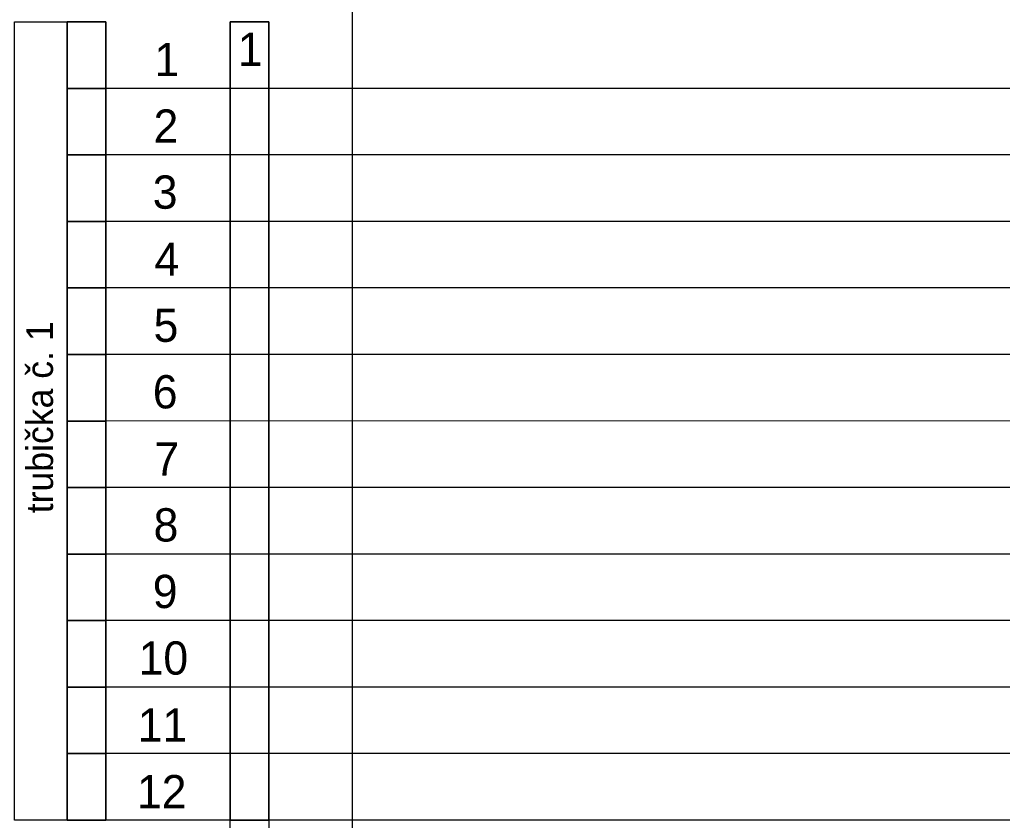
# Model space of a CAD drawing. Extents: x 1901 to 2519, y -3585 to -3154.
# Drawn here: x 2387.9 to 2439.8, y -3245.2 to -3202.9 of the extents above; entities that cross this region are included whole.
import ezdxf

# ---------------------------------------------------------------- set-up
doc = ezdxf.new("R2010")
doc.units = 0
doc.layers.add('rozvláknění', color=7, linetype='Continuous')

msp = doc.modelspace()

# ---------------------------------------------------------------- linework, layer by layer
at = {"layer": 'rozvláknění'}
for p, q in [((2487.131, -3206.524), (2392.43, -3206.525)), ((2487.131, -3210.042), (2392.43, -3210.043)), ((2487.131, -3213.56), (2392.43, -3213.561)), ((2487.131, -3217.078), (2392.43, -3217.079)), ((2487.131, -3220.596), (2392.43, -3220.598)), ((2487.131, -3224.115), (2392.43, -3224.116)), ((2487.131, -3227.633), (2392.43, -3227.634)), ((2487.131, -3231.151), (2392.43, -3231.152)), ((2487.131, -3234.669), (2392.43, -3234.67)), ((2487.131, -3238.187), (2392.43, -3238.189)), ((2487.131, -3241.706), (2392.43, -3241.707)), ((2487.131, -3245.224), (2392.43, -3245.225))]:
    msp.add_line(p, q, dxfattribs=at)
for points in [[(2371.457, -3178.543), (2405.455, -3178.542), (2405.455, -3379.276), (2371.457, -3379.276)], [(2387.602, -3203.007), (2390.389, -3203.007), (2390.389, -3245.221), (2387.602, -3245.221)], [(2390.389, -3203.007), (2392.43, -3203.007), (2392.43, -3206.525), (2390.389, -3206.525)], [(2390.389, -3203.007), (2392.43, -3203.007), (2392.43, -3206.525), (2390.389, -3206.525)], [(2401.054, -3287.479), (2399.013, -3287.479), (2399.013, -3203.007), (2401.054, -3203.007)], [(2401.054, -3245.225), (2399.013, -3245.225), (2399.013, -3203.007), (2401.054, -3203.007)], [(2390.389, -3206.525), (2392.43, -3206.525), (2392.43, -3210.043), (2390.389, -3210.043)], [(2390.389, -3206.525), (2392.43, -3206.525), (2392.43, -3210.043), (2390.389, -3210.043)], [(2390.389, -3210.043), (2392.43, -3210.043), (2392.43, -3213.561), (2390.389, -3213.561)], [(2390.389, -3210.043), (2392.43, -3210.043), (2392.43, -3213.561), (2390.389, -3213.561)], [(2390.389, -3213.561), (2392.43, -3213.561), (2392.43, -3217.079), (2390.389, -3217.079)], [(2390.389, -3213.561), (2392.43, -3213.561), (2392.43, -3217.079), (2390.389, -3217.079)], [(2390.389, -3217.079), (2392.43, -3217.079), (2392.43, -3220.598), (2390.389, -3220.598)], [(2390.389, -3217.079), (2392.43, -3217.079), (2392.43, -3220.598), (2390.389, -3220.598)], [(2390.389, -3220.598), (2392.43, -3220.598), (2392.43, -3224.116), (2390.389, -3224.116)], [(2390.389, -3220.598), (2392.43, -3220.598), (2392.43, -3224.116), (2390.389, -3224.116)], [(2390.389, -3224.116), (2392.43, -3224.116), (2392.43, -3227.634), (2390.389, -3227.634)], [(2390.389, -3224.116), (2392.43, -3224.116), (2392.43, -3227.634), (2390.389, -3227.634)], [(2390.389, -3227.634), (2392.43, -3227.634), (2392.43, -3231.152), (2390.389, -3231.152)], [(2390.389, -3227.634), (2392.43, -3227.634), (2392.43, -3231.152), (2390.389, -3231.152)], [(2390.389, -3231.152), (2392.43, -3231.152), (2392.43, -3234.67), (2390.389, -3234.67)], [(2390.389, -3231.152), (2392.43, -3231.152), (2392.43, -3234.67), (2390.389, -3234.67)], [(2390.389, -3234.67), (2392.43, -3234.67), (2392.43, -3238.189), (2390.389, -3238.189)], [(2390.389, -3234.67), (2392.43, -3234.67), (2392.43, -3238.189), (2390.389, -3238.189)], [(2390.389, -3238.189), (2392.43, -3238.189), (2392.43, -3241.707), (2390.389, -3241.707)], [(2390.389, -3238.189), (2392.43, -3238.189), (2392.43, -3241.707), (2390.389, -3241.707)], [(2390.389, -3241.707), (2392.43, -3241.707), (2392.43, -3245.225), (2390.389, -3245.225)], [(2390.389, -3241.707), (2392.43, -3241.707), (2392.43, -3245.225), (2390.389, -3245.225)]]:
    msp.add_lwpolyline(points, close=True, dxfattribs=at)
for points in [[(2390.389, -3206.525), (2392.43, -3206.525), (2392.43, -3203.007), (2390.389, -3203.007), (2390.389, -3206.525)], [(2390.389, -3206.525), (2392.43, -3206.525), (2392.43, -3203.007), (2390.389, -3203.007), (2390.389, -3206.525)], [(2390.389, -3206.525), (2392.43, -3206.525), (2392.43, -3203.007), (2390.389, -3203.007), (2390.389, -3206.525)], [(2390.389, -3206.525), (2392.43, -3206.525), (2392.43, -3203.007), (2390.389, -3203.007), (2390.389, -3206.525)], [(2390.389, -3206.525), (2392.43, -3206.525), (2392.43, -3203.007), (2390.389, -3203.007), (2390.389, -3206.525)], [(2390.389, -3206.525), (2392.43, -3206.525), (2392.43, -3203.007), (2390.389, -3203.007), (2390.389, -3206.525)], [(2390.389, -3206.525), (2392.43, -3206.525), (2392.43, -3203.007), (2390.389, -3203.007), (2390.389, -3206.525)], [(2390.389, -3206.525), (2392.43, -3206.525), (2392.43, -3203.007), (2390.389, -3203.007), (2390.389, -3206.525)], [(2390.389, -3206.525), (2392.43, -3206.525), (2392.43, -3203.007), (2390.389, -3203.007), (2390.389, -3206.525)], [(2390.389, -3206.525), (2392.43, -3206.525), (2392.43, -3203.007), (2390.389, -3203.007), (2390.389, -3206.525)], [(2401.054, -3203.007), (2399.013, -3203.007), (2399.013, -3245.225), (2401.054, -3245.225), (2401.054, -3203.007)], [(2401.054, -3203.007), (2399.013, -3203.007), (2399.013, -3245.225), (2401.054, -3245.225), (2401.054, -3203.007)], [(2401.054, -3203.007), (2399.013, -3203.007), (2399.013, -3245.225), (2401.054, -3245.225), (2401.054, -3203.007)], [(2401.054, -3203.007), (2399.013, -3203.007), (2399.013, -3245.225), (2401.054, -3245.225), (2401.054, -3203.007)], [(2401.054, -3203.007), (2399.013, -3203.007), (2399.013, -3245.225), (2401.054, -3245.225), (2401.054, -3203.007)], [(2401.054, -3203.007), (2399.013, -3203.007), (2399.013, -3245.225), (2401.054, -3245.225), (2401.054, -3203.007)], [(2390.389, -3210.043), (2392.43, -3210.043), (2392.43, -3206.525), (2390.389, -3206.525), (2390.389, -3210.043)], [(2390.389, -3210.043), (2392.43, -3210.043), (2392.43, -3206.525), (2390.389, -3206.525), (2390.389, -3210.043)], [(2390.389, -3210.043), (2392.43, -3210.043), (2392.43, -3206.525), (2390.389, -3206.525), (2390.389, -3210.043)], [(2390.389, -3210.043), (2392.43, -3210.043), (2392.43, -3206.525), (2390.389, -3206.525), (2390.389, -3210.043)], [(2390.389, -3210.043), (2392.43, -3210.043), (2392.43, -3206.525), (2390.389, -3206.525), (2390.389, -3210.043)], [(2390.389, -3210.043), (2392.43, -3210.043), (2392.43, -3206.525), (2390.389, -3206.525), (2390.389, -3210.043)], [(2390.389, -3210.043), (2392.43, -3210.043), (2392.43, -3206.525), (2390.389, -3206.525), (2390.389, -3210.043)], [(2390.389, -3210.043), (2392.43, -3210.043), (2392.43, -3206.525), (2390.389, -3206.525), (2390.389, -3210.043)], [(2390.389, -3210.043), (2392.43, -3210.043), (2392.43, -3206.525), (2390.389, -3206.525), (2390.389, -3210.043)], [(2390.389, -3210.043), (2392.43, -3210.043), (2392.43, -3206.525), (2390.389, -3206.525), (2390.389, -3210.043)], [(2390.389, -3213.561), (2392.43, -3213.561), (2392.43, -3210.043), (2390.389, -3210.043), (2390.389, -3213.561)], [(2390.389, -3213.561), (2392.43, -3213.561), (2392.43, -3210.043), (2390.389, -3210.043), (2390.389, -3213.561)], [(2390.389, -3213.561), (2392.43, -3213.561), (2392.43, -3210.043), (2390.389, -3210.043), (2390.389, -3213.561)], [(2390.389, -3213.561), (2392.43, -3213.561), (2392.43, -3210.043), (2390.389, -3210.043), (2390.389, -3213.561)], [(2390.389, -3213.561), (2392.43, -3213.561), (2392.43, -3210.043), (2390.389, -3210.043), (2390.389, -3213.561)], [(2390.389, -3213.561), (2392.43, -3213.561), (2392.43, -3210.043), (2390.389, -3210.043), (2390.389, -3213.561)], [(2390.389, -3213.561), (2392.43, -3213.561), (2392.43, -3210.043), (2390.389, -3210.043), (2390.389, -3213.561)], [(2390.389, -3213.561), (2392.43, -3213.561), (2392.43, -3210.043), (2390.389, -3210.043), (2390.389, -3213.561)], [(2390.389, -3213.561), (2392.43, -3213.561), (2392.43, -3210.043), (2390.389, -3210.043), (2390.389, -3213.561)], [(2390.389, -3213.561), (2392.43, -3213.561), (2392.43, -3210.043), (2390.389, -3210.043), (2390.389, -3213.561)], [(2390.389, -3217.079), (2392.43, -3217.079), (2392.43, -3213.561), (2390.389, -3213.561), (2390.389, -3217.079)], [(2390.389, -3217.079), (2392.43, -3217.079), (2392.43, -3213.561), (2390.389, -3213.561), (2390.389, -3217.079)], [(2390.389, -3217.079), (2392.43, -3217.079), (2392.43, -3213.561), (2390.389, -3213.561), (2390.389, -3217.079)], [(2390.389, -3217.079), (2392.43, -3217.079), (2392.43, -3213.561), (2390.389, -3213.561), (2390.389, -3217.079)], [(2390.389, -3217.079), (2392.43, -3217.079), (2392.43, -3213.561), (2390.389, -3213.561), (2390.389, -3217.079)], [(2390.389, -3217.079), (2392.43, -3217.079), (2392.43, -3213.561), (2390.389, -3213.561), (2390.389, -3217.079)], [(2390.389, -3217.079), (2392.43, -3217.079), (2392.43, -3213.561), (2390.389, -3213.561), (2390.389, -3217.079)], [(2390.389, -3217.079), (2392.43, -3217.079), (2392.43, -3213.561), (2390.389, -3213.561), (2390.389, -3217.079)], [(2390.389, -3217.079), (2392.43, -3217.079), (2392.43, -3213.561), (2390.389, -3213.561), (2390.389, -3217.079)], [(2390.389, -3217.079), (2392.43, -3217.079), (2392.43, -3213.561), (2390.389, -3213.561), (2390.389, -3217.079)], [(2390.389, -3220.598), (2392.43, -3220.598), (2392.43, -3217.079), (2390.389, -3217.079), (2390.389, -3220.598)], [(2390.389, -3220.598), (2392.43, -3220.598), (2392.43, -3217.079), (2390.389, -3217.079), (2390.389, -3220.598)], [(2390.389, -3220.598), (2392.43, -3220.598), (2392.43, -3217.079), (2390.389, -3217.079), (2390.389, -3220.598)], [(2390.389, -3220.598), (2392.43, -3220.598), (2392.43, -3217.079), (2390.389, -3217.079), (2390.389, -3220.598)], [(2390.389, -3220.598), (2392.43, -3220.598), (2392.43, -3217.079), (2390.389, -3217.079), (2390.389, -3220.598)], [(2390.389, -3220.598), (2392.43, -3220.598), (2392.43, -3217.079), (2390.389, -3217.079), (2390.389, -3220.598)], [(2390.389, -3220.598), (2392.43, -3220.598), (2392.43, -3217.079), (2390.389, -3217.079), (2390.389, -3220.598)], [(2390.389, -3220.598), (2392.43, -3220.598), (2392.43, -3217.079), (2390.389, -3217.079), (2390.389, -3220.598)], [(2390.389, -3220.598), (2392.43, -3220.598), (2392.43, -3217.079), (2390.389, -3217.079), (2390.389, -3220.598)], [(2390.389, -3220.598), (2392.43, -3220.598), (2392.43, -3217.079), (2390.389, -3217.079), (2390.389, -3220.598)], [(2390.389, -3224.116), (2392.43, -3224.116), (2392.43, -3220.598), (2390.389, -3220.598), (2390.389, -3224.116)], [(2390.389, -3224.116), (2392.43, -3224.116), (2392.43, -3220.598), (2390.389, -3220.598), (2390.389, -3224.116)], [(2390.389, -3224.116), (2392.43, -3224.116), (2392.43, -3220.598), (2390.389, -3220.598), (2390.389, -3224.116)], [(2390.389, -3224.116), (2392.43, -3224.116), (2392.43, -3220.598), (2390.389, -3220.598), (2390.389, -3224.116)], [(2390.389, -3224.116), (2392.43, -3224.116), (2392.43, -3220.598), (2390.389, -3220.598), (2390.389, -3224.116)], [(2390.389, -3224.116), (2392.43, -3224.116), (2392.43, -3220.598), (2390.389, -3220.598), (2390.389, -3224.116)], [(2390.389, -3224.116), (2392.43, -3224.116), (2392.43, -3220.598), (2390.389, -3220.598), (2390.389, -3224.116)], [(2390.389, -3224.116), (2392.43, -3224.116), (2392.43, -3220.598), (2390.389, -3220.598), (2390.389, -3224.116)], [(2390.389, -3224.116), (2392.43, -3224.116), (2392.43, -3220.598), (2390.389, -3220.598), (2390.389, -3224.116)], [(2390.389, -3224.116), (2392.43, -3224.116), (2392.43, -3220.598), (2390.389, -3220.598), (2390.389, -3224.116)], [(2390.389, -3227.634), (2392.43, -3227.634), (2392.43, -3224.116), (2390.389, -3224.116), (2390.389, -3227.634)], [(2390.389, -3227.634), (2392.43, -3227.634), (2392.43, -3224.116), (2390.389, -3224.116), (2390.389, -3227.634)], [(2390.389, -3227.634), (2392.43, -3227.634), (2392.43, -3224.116), (2390.389, -3224.116), (2390.389, -3227.634)], [(2390.389, -3227.634), (2392.43, -3227.634), (2392.43, -3224.116), (2390.389, -3224.116), (2390.389, -3227.634)], [(2390.389, -3227.634), (2392.43, -3227.634), (2392.43, -3224.116), (2390.389, -3224.116), (2390.389, -3227.634)], [(2390.389, -3227.634), (2392.43, -3227.634), (2392.43, -3224.116), (2390.389, -3224.116), (2390.389, -3227.634)], [(2390.389, -3227.634), (2392.43, -3227.634), (2392.43, -3224.116), (2390.389, -3224.116), (2390.389, -3227.634)], [(2390.389, -3227.634), (2392.43, -3227.634), (2392.43, -3224.116), (2390.389, -3224.116), (2390.389, -3227.634)], [(2390.389, -3227.634), (2392.43, -3227.634), (2392.43, -3224.116), (2390.389, -3224.116), (2390.389, -3227.634)], [(2390.389, -3227.634), (2392.43, -3227.634), (2392.43, -3224.116), (2390.389, -3224.116), (2390.389, -3227.634)], [(2390.389, -3231.152), (2392.43, -3231.152), (2392.43, -3227.634), (2390.389, -3227.634), (2390.389, -3231.152)], [(2390.389, -3231.152), (2392.43, -3231.152), (2392.43, -3227.634), (2390.389, -3227.634), (2390.389, -3231.152)], [(2390.389, -3231.152), (2392.43, -3231.152), (2392.43, -3227.634), (2390.389, -3227.634), (2390.389, -3231.152)], [(2390.389, -3231.152), (2392.43, -3231.152), (2392.43, -3227.634), (2390.389, -3227.634), (2390.389, -3231.152)], [(2390.389, -3231.152), (2392.43, -3231.152), (2392.43, -3227.634), (2390.389, -3227.634), (2390.389, -3231.152)], [(2390.389, -3231.152), (2392.43, -3231.152), (2392.43, -3227.634), (2390.389, -3227.634), (2390.389, -3231.152)], [(2390.389, -3231.152), (2392.43, -3231.152), (2392.43, -3227.634), (2390.389, -3227.634), (2390.389, -3231.152)], [(2390.389, -3231.152), (2392.43, -3231.152), (2392.43, -3227.634), (2390.389, -3227.634), (2390.389, -3231.152)], [(2390.389, -3231.152), (2392.43, -3231.152), (2392.43, -3227.634), (2390.389, -3227.634), (2390.389, -3231.152)], [(2390.389, -3231.152), (2392.43, -3231.152), (2392.43, -3227.634), (2390.389, -3227.634), (2390.389, -3231.152)], [(2390.389, -3234.67), (2392.43, -3234.67), (2392.43, -3231.152), (2390.389, -3231.152), (2390.389, -3234.67)], [(2390.389, -3234.67), (2392.43, -3234.67), (2392.43, -3231.152), (2390.389, -3231.152), (2390.389, -3234.67)], [(2390.389, -3234.67), (2392.43, -3234.67), (2392.43, -3231.152), (2390.389, -3231.152), (2390.389, -3234.67)], [(2390.389, -3234.67), (2392.43, -3234.67), (2392.43, -3231.152), (2390.389, -3231.152), (2390.389, -3234.67)], [(2390.389, -3234.67), (2392.43, -3234.67), (2392.43, -3231.152), (2390.389, -3231.152), (2390.389, -3234.67)], [(2390.389, -3234.67), (2392.43, -3234.67), (2392.43, -3231.152), (2390.389, -3231.152), (2390.389, -3234.67)], [(2390.389, -3234.67), (2392.43, -3234.67), (2392.43, -3231.152), (2390.389, -3231.152), (2390.389, -3234.67)], [(2390.389, -3234.67), (2392.43, -3234.67), (2392.43, -3231.152), (2390.389, -3231.152), (2390.389, -3234.67)], [(2390.389, -3234.67), (2392.43, -3234.67), (2392.43, -3231.152), (2390.389, -3231.152), (2390.389, -3234.67)], [(2390.389, -3234.67), (2392.43, -3234.67), (2392.43, -3231.152), (2390.389, -3231.152), (2390.389, -3234.67)], [(2390.389, -3238.189), (2392.43, -3238.189), (2392.43, -3234.67), (2390.389, -3234.67), (2390.389, -3238.189)], [(2390.389, -3238.189), (2392.43, -3238.189), (2392.43, -3234.67), (2390.389, -3234.67), (2390.389, -3238.189)], [(2390.389, -3238.189), (2392.43, -3238.189), (2392.43, -3234.67), (2390.389, -3234.67), (2390.389, -3238.189)], [(2390.389, -3238.189), (2392.43, -3238.189), (2392.43, -3234.67), (2390.389, -3234.67), (2390.389, -3238.189)], [(2390.389, -3238.189), (2392.43, -3238.189), (2392.43, -3234.67), (2390.389, -3234.67), (2390.389, -3238.189)], [(2390.389, -3238.189), (2392.43, -3238.189), (2392.43, -3234.67), (2390.389, -3234.67), (2390.389, -3238.189)], [(2390.389, -3238.189), (2392.43, -3238.189), (2392.43, -3234.67), (2390.389, -3234.67), (2390.389, -3238.189)], [(2390.389, -3238.189), (2392.43, -3238.189), (2392.43, -3234.67), (2390.389, -3234.67), (2390.389, -3238.189)], [(2390.389, -3238.189), (2392.43, -3238.189), (2392.43, -3234.67), (2390.389, -3234.67), (2390.389, -3238.189)], [(2390.389, -3238.189), (2392.43, -3238.189), (2392.43, -3234.67), (2390.389, -3234.67), (2390.389, -3238.189)], [(2390.389, -3241.707), (2392.43, -3241.707), (2392.43, -3238.189), (2390.389, -3238.189), (2390.389, -3241.707)], [(2390.389, -3241.707), (2392.43, -3241.707), (2392.43, -3238.189), (2390.389, -3238.189), (2390.389, -3241.707)], [(2390.389, -3241.707), (2392.43, -3241.707), (2392.43, -3238.189), (2390.389, -3238.189), (2390.389, -3241.707)], [(2390.389, -3241.707), (2392.43, -3241.707), (2392.43, -3238.189), (2390.389, -3238.189), (2390.389, -3241.707)], [(2390.389, -3241.707), (2392.43, -3241.707), (2392.43, -3238.189), (2390.389, -3238.189), (2390.389, -3241.707)], [(2390.389, -3241.707), (2392.43, -3241.707), (2392.43, -3238.189), (2390.389, -3238.189), (2390.389, -3241.707)], [(2390.389, -3241.707), (2392.43, -3241.707), (2392.43, -3238.189), (2390.389, -3238.189), (2390.389, -3241.707)], [(2390.389, -3241.707), (2392.43, -3241.707), (2392.43, -3238.189), (2390.389, -3238.189), (2390.389, -3241.707)], [(2390.389, -3241.707), (2392.43, -3241.707), (2392.43, -3238.189), (2390.389, -3238.189), (2390.389, -3241.707)], [(2390.389, -3241.707), (2392.43, -3241.707), (2392.43, -3238.189), (2390.389, -3238.189), (2390.389, -3241.707)], [(2390.389, -3245.225), (2392.43, -3245.225), (2392.43, -3241.707), (2390.389, -3241.707), (2390.389, -3245.225)], [(2390.389, -3245.225), (2392.43, -3245.225), (2392.43, -3241.707), (2390.389, -3241.707), (2390.389, -3245.225)], [(2390.389, -3245.225), (2392.43, -3245.225), (2392.43, -3241.707), (2390.389, -3241.707), (2390.389, -3245.225)], [(2390.389, -3245.225), (2392.43, -3245.225), (2392.43, -3241.707), (2390.389, -3241.707), (2390.389, -3245.225)], [(2390.389, -3245.225), (2392.43, -3245.225), (2392.43, -3241.707), (2390.389, -3241.707), (2390.389, -3245.225)], [(2390.389, -3245.225), (2392.43, -3245.225), (2392.43, -3241.707), (2390.389, -3241.707), (2390.389, -3245.225)], [(2390.389, -3245.225), (2392.43, -3245.225), (2392.43, -3241.707), (2390.389, -3241.707), (2390.389, -3245.225)], [(2390.389, -3245.225), (2392.43, -3245.225), (2392.43, -3241.707), (2390.389, -3241.707), (2390.389, -3245.225)], [(2390.389, -3245.225), (2392.43, -3245.225), (2392.43, -3241.707), (2390.389, -3241.707), (2390.389, -3245.225)], [(2390.389, -3245.225), (2392.43, -3245.225), (2392.43, -3241.707), (2390.389, -3241.707), (2390.389, -3245.225)]]:
    msp.add_lwpolyline(points, dxfattribs=at)

# ---------------------------------------------------------------- texts
for s, p in [('1', (2399.411, -3205.332)), ('1', (2399.411, -3205.332)), ('1', (2395.003, -3205.878)), ('2', (2394.956, -3209.398)), ('3', (2394.914, -3212.889)), ('4', (2395.003, -3216.438)), ('5', (2394.956, -3219.929)), ('6', (2394.914, -3223.449)), ('7', (2395.003, -3226.998)), ('8', (2394.956, -3230.489)), ('9', (2394.914, -3234.009)), ('10', (2394.166, -3237.529)), ('11', (2394.119, -3241.078)), ('12', (2394.077, -3244.598))]:
    msp.add_text(s, height=1.76, dxfattribs=at).set_placement(p)
msp.add_text('trubička č. 1', height=1.408, rotation=90, dxfattribs=at).set_placement((2389.637, -3228.996))

doc.saveas('drawing.dxf')
